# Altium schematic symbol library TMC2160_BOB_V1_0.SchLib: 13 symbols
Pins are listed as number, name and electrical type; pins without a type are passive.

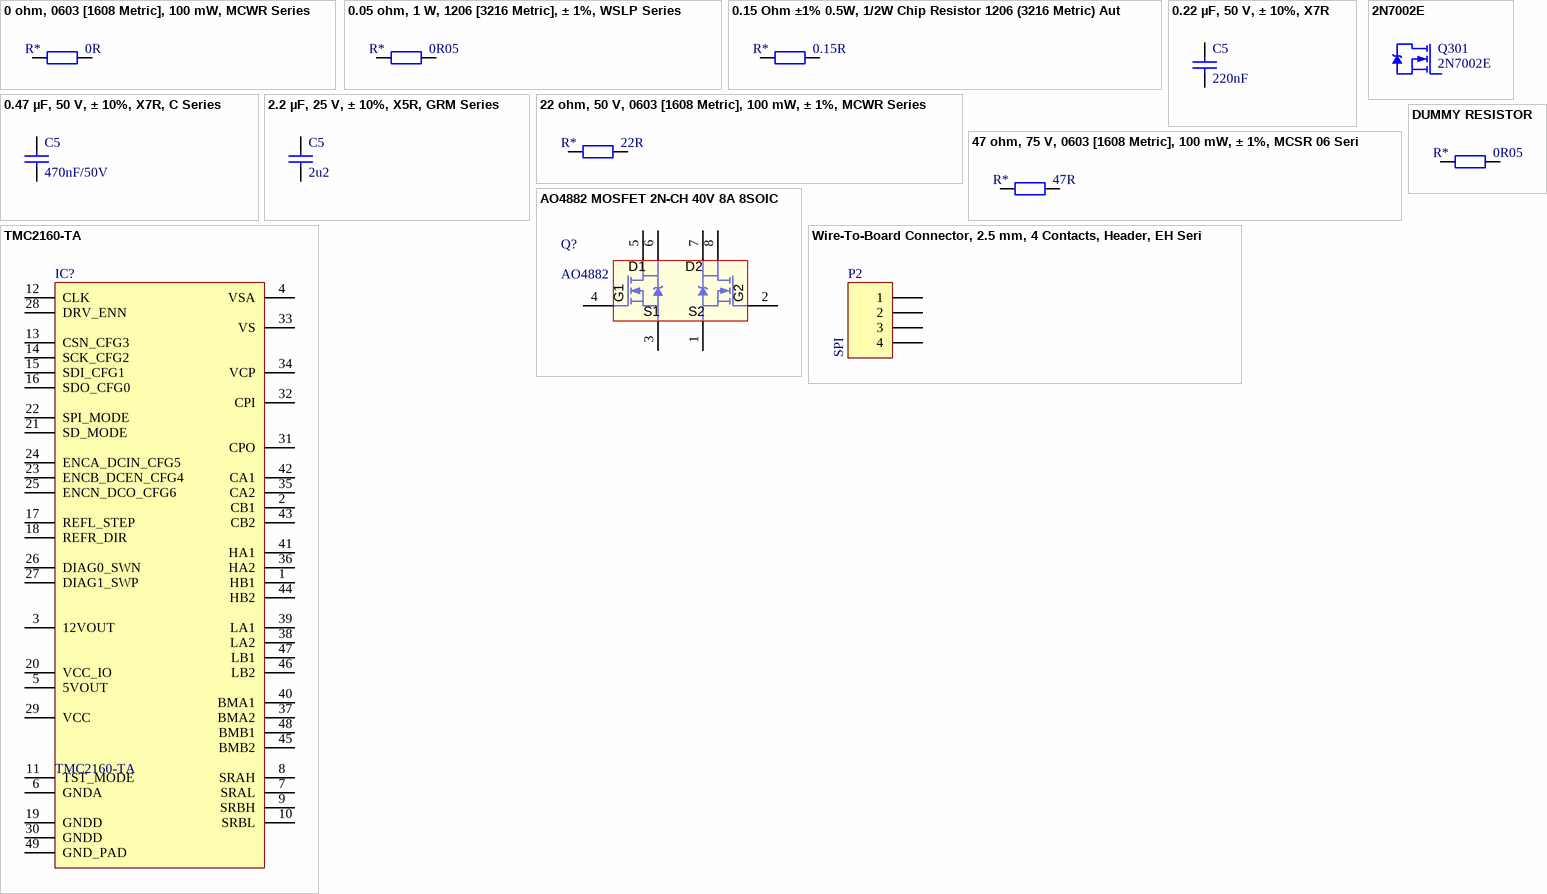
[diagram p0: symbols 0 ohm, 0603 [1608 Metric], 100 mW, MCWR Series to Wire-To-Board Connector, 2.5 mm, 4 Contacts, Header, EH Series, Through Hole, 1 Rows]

## 0 ohm, 0603 [1608 Metric], 100 mW, MCWR Series
designator R*, comment 0R
SMD Chip Resistor, Thick Film, 0 ohm, 0603 [1608 Metric], 100 mW, MCWR Series; MPN: MCWR06X000 PTL; Temp coefficient: *ppm; PowerRating: 100mW; MF: MULTICOMP
footprint R0402 (0402 resistor)
footprint R0603 (0603 resistor)
footprint R0805 (0805 resistor)
footprint R1206 (1206 resistor)
footprint R2512 (2512 resistor)
footprint R0201 (0201 resistor)
footprint R1210 (1210 resistor)
footprint R1812 (1812 resistor)
footprint R2010 (2010 resistor)
footprint R2512 (2512 resistor)
pins: 1, 2

## 0.05 ohm, 1 W, 1206 [3216 Metric], ± 1%, WSLP Series
designator R*, comment Resistance: 0R05  (hidden comment: 0R05 / 1W / 1%)
SMD Current Sense Resistor, 0.05 ohm, 1 W, 1206 [3216 Metric], ± 1%, WSLP Series; MPN: WSLP1206R0500FEA; Temp coefficient: *ppm; MF: VISHAY
footprint R0402 (0402 resistor)
footprint R0603 (0603 resistor)
footprint R0805 (0805 resistor)
footprint R1206 (1206 resistor)
footprint R2512 (2512 resistor)
footprint R0201 (0201 resistor)
footprint R1210 (1210 resistor)
footprint R1812 (1812 resistor)
footprint R2010 (2010 resistor)
footprint R2512 (2512 resistor)
pins: 1, 2

## 0.15 Ohm ±1% 0.5W, 1/2W Chip Resistor 1206 (3216 Metric) Automotive AEC-Q200, Current Sense Thick Film
designator R*, comment Resistance: 0.15R  (hidden comment: 0.15R / 0.5W / 1%)
0.15 Ohm ±1% 0.5W, 1/2W Chip Resistor 1206 (3216 Metric) Automotive AEC-Q200, Current Sense Thick Film; MPN: ERJ-8BSFR15V; Temp coefficient: *ppm; MF: Panasonic
footprint R0402 (0402 resistor)
footprint R0603 (0603 resistor)
footprint R0805 (0805 resistor)
footprint R1206 (1206 resistor)
footprint R2512 (2512 resistor)
footprint R0201 (0201 resistor)
footprint R1210 (1210 resistor)
footprint R1812 (1812 resistor)
footprint R2010 (2010 resistor)
footprint R2512 (2512 resistor)
pins: 1, 2

## 0.22 µF, 50 V, ± 10%, X7R
designator C5, comment 220nF
SMD Multilayer Ceramic Capacitor, 0603 [1608 Metric], 0.22 µF, 50 V, ± 10%, X7R, GCM Series; MPN: GCM188R71H224KA64D; Type: MLCC; Voltage rating: 50V; ComponentLinknDescription: Datasheet; MF: MURATA
footprint C0402 (0402 ceramic capacitor)
footprint C0603 (0603 ceramic capacitor)
footprint C0805 (0805 ceramic capacitor)
footprint C1206 (1206 ceramic capacitor)
footprint C1210 (1210 capacitor)
footprint C1812 (1812 capacitor)
pins: 1, 2

## 0.47 µF, 50 V, ± 10%, X7R, C Series
designator C5, comment 470nF/50V
SMD Multilayer Ceramic Capacitor, 0603 [1608 Metric], 0.47 µF, 50 V, ± 10%, X7R, C Series; MPN: C1608X7R1H474K080AC; Type: MLCC; VoltageRating: 50V; ComponentLinknDescription: Datasheet; MF: TDK; Capacitance: 470nF
footprint C0402 (0402 ceramic capacitor)
footprint C0603 (0603 ceramic capacitor)
footprint C0805 (0805 ceramic capacitor)
footprint C1206 (1206 ceramic capacitor)
footprint C1210 (1210 capacitor)
footprint C1812 (1812 capacitor)
pins: 1, 2

## 2.2 µF, 25 V, ± 10%, X5R, GRM Series
designator C5, comment 2u2
SMD Multilayer Ceramic Capacitor, 0603 [1608 Metric], 2.2 µF, 25 V, ± 10%, X5R, GRM Series; MPN: GRM188R61E225KA12D; Type: MLCC; Voltage rating: 50V; ComponentLinknDescription: Datasheet; MF: MURATA
footprint C0402 (0402 ceramic capacitor)
footprint C0603 (0603 ceramic capacitor)
footprint C0805 (0805 ceramic capacitor)
footprint C1206 (1206 ceramic capacitor)
footprint C1210 (1210 capacitor)
footprint C1812 (1812 capacitor)
pins: 1, 2

## 2N7002E
designator Q301
N-MOSFET 60V 310mA
footprint SOT-23 (SOT23, 3-Leads, Body 2,90x2,45mm, Pitch 0,95mm)

## 22 ohm, 50 V, 0603 [1608 Metric], 100 mW, ± 1%, MCWR Series
designator R*, comment Resistance: 22R  (hidden comment: 22R / 100mW / 1%)
SMD Chip Resistor, Thick Film, 22 ohm, 50 V, 0603 [1608 Metric], 100 mW, ± 1%, MCWR Series; MPN: MCWR06X22R0FTLV; Temp coefficient: *ppm; MF: MULTICOMP
footprint R0402 (0402 resistor)
footprint R0603 (0603 resistor)
footprint R0805 (0805 resistor)
footprint R1206 (1206 resistor)
footprint R2512 (2512 resistor)
footprint R0201 (0201 resistor)
footprint R1210 (1210 resistor)
footprint R1812 (1812 resistor)
footprint R2010 (2010 resistor)
footprint R2512 (2512 resistor)
pins: 1, 2

## 47 ohm, 75 V, 0603 [1608 Metric], 100 mW, ± 1%, MCSR 06 Series
designator R*, comment Resistance: 47R  (hidden comment: 47R /  / 1%)
SMD Chip Resistor, Ceramic, 47 ohm, 75 V, 0603 [1608 Metric], 100 mW, ± 1%, MCSR 06 Series; MPN: MCSR06X47R0FTL; Temp coefficient: *ppm; MF: MULTICOMP
footprint R0402 (0402 resistor)
footprint R0603 (0603 resistor)
footprint R0805 (0805 resistor)
footprint R1206 (1206 resistor)
footprint R2512 (2512 resistor)
footprint R0201 (0201 resistor)
footprint R1210 (1210 resistor)
footprint R1812 (1812 resistor)
footprint R2010 (2010 resistor)
footprint R2512 (2512 resistor)
pins: 1, 2

## AO4882 MOSFET 2N-CH 40V 8A 8SOIC
designator Q?, comment AO4882
Mosfet Array 2 N-Channel (Dual) 40V 8A 2W Surface Mount 8-SOIC; MF: Alpha & Omega Semiconductor Inc.
footprint SOP127P600X170-8L (SOP, 8-Leads, Body 4,90x3,90mm, Pitch 1,27mm, IPC High Density)
pins: 1 S2, 2 G2, 3 S1, 4 G1, 5 D1, 6 D1, 7 D2, 8 D2

## DUMMY RESISTOR
designator R*, comment Resistance: 0R05  (hidden comment: 0R05 /  /)
Temp coefficient: *ppm
footprint R0402 (0402 resistor)
footprint R0603 (0603 resistor)
footprint R0805 (0805 resistor)
footprint R1206 (1206 resistor)
footprint R2512 (2512 resistor)
footprint R0201 (0201 resistor)
footprint R1210 (1210 resistor)
footprint R1812 (1812 resistor)
footprint R2010 (2010 resistor)
footprint R2512 (2512 resistor)
pins: 1, 2

## TMC2160-TA
designator IC?
Manufacturer: TRINAMIC; Geometry.Height: 1,2mm
footprint TMC5160_TSQFP50P900X900X120_HS-49L (TSQFP, 48-Leads, Body 7,00x7,00mm, Pitch 0,50mm, Thermal Pad 5,10x5,10mm, IPC High Density)
pins: 1 HB1, 2 CB1, 3 12VOUT, 4 VSA, 5 5VOUT, 6 GNDA, 7 SRAL, 8 SRAH, 9 SRBH, 10 SRBL, 11 TST_MODE, 12 CLK, 13 CSN_CFG3, 14 SCK_CFG2, 15 SDI_CFG1, 16 SDO_CFG0, 17 REFL_STEP, 18 REFR_DIR, 19 GNDD, 20 VCC_IO, 21 SD_MODE, 22 SPI_MODE, 23 ENCB_DCEN_CFG4, 24 ENCA_DCIN_CFG5, 25 ENCN_DCO_CFG6, 26 DIAG0_SWN, 27 DIAG1_SWP, 28 DRV_ENN, 29 VCC, 30 GNDD, 31 CPO, 32 CPI, 33 VS, 34 VCP, 35 CA2, 36 HA2, 37 BMA2, 38 LA2, 39 LA1, 40 BMA1, 41 HA1, 42 CA1, 43 CB2, 44 HB2, 45 BMB2, 46 LB2, 47 LB1, 48 BMB1, 49 GND_PAD

## Wire-To-Board Connector, 2.5 mm, 4 Contacts, Header, EH Series, Through Hole, 1 Rows
designator P2, comment SPI
Wire-To-Board Connector, 2.5 mm, 4 Contacts, Header, EH Series, Through Hole, 1 Rows; MPN: B4B-EH-A; MF: JST (JAPAN SOLDERLESS TERMINALS)
signal-integrity model Connector
footprint B4B-EH-A
pins: 1, 2, 3, 4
